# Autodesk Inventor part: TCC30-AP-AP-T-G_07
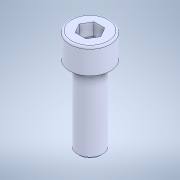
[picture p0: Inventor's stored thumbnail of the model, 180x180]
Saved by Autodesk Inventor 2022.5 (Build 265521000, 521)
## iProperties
Created: 2023-09
Part Number: TCC30-AP-AP-T-G_07
Material: 一般
Document SubType Name: Modeling
Designer: ImaoCorp
Density: 1 g/cm^3
Appearance: 既定
Author: ImaoCorp
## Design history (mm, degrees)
feature "TCC30-AP-AP-T-G_07"
node "ソリッド1"
